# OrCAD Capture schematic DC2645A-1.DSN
size Custom; note: WIDEBAND IQ DEMODULATOR
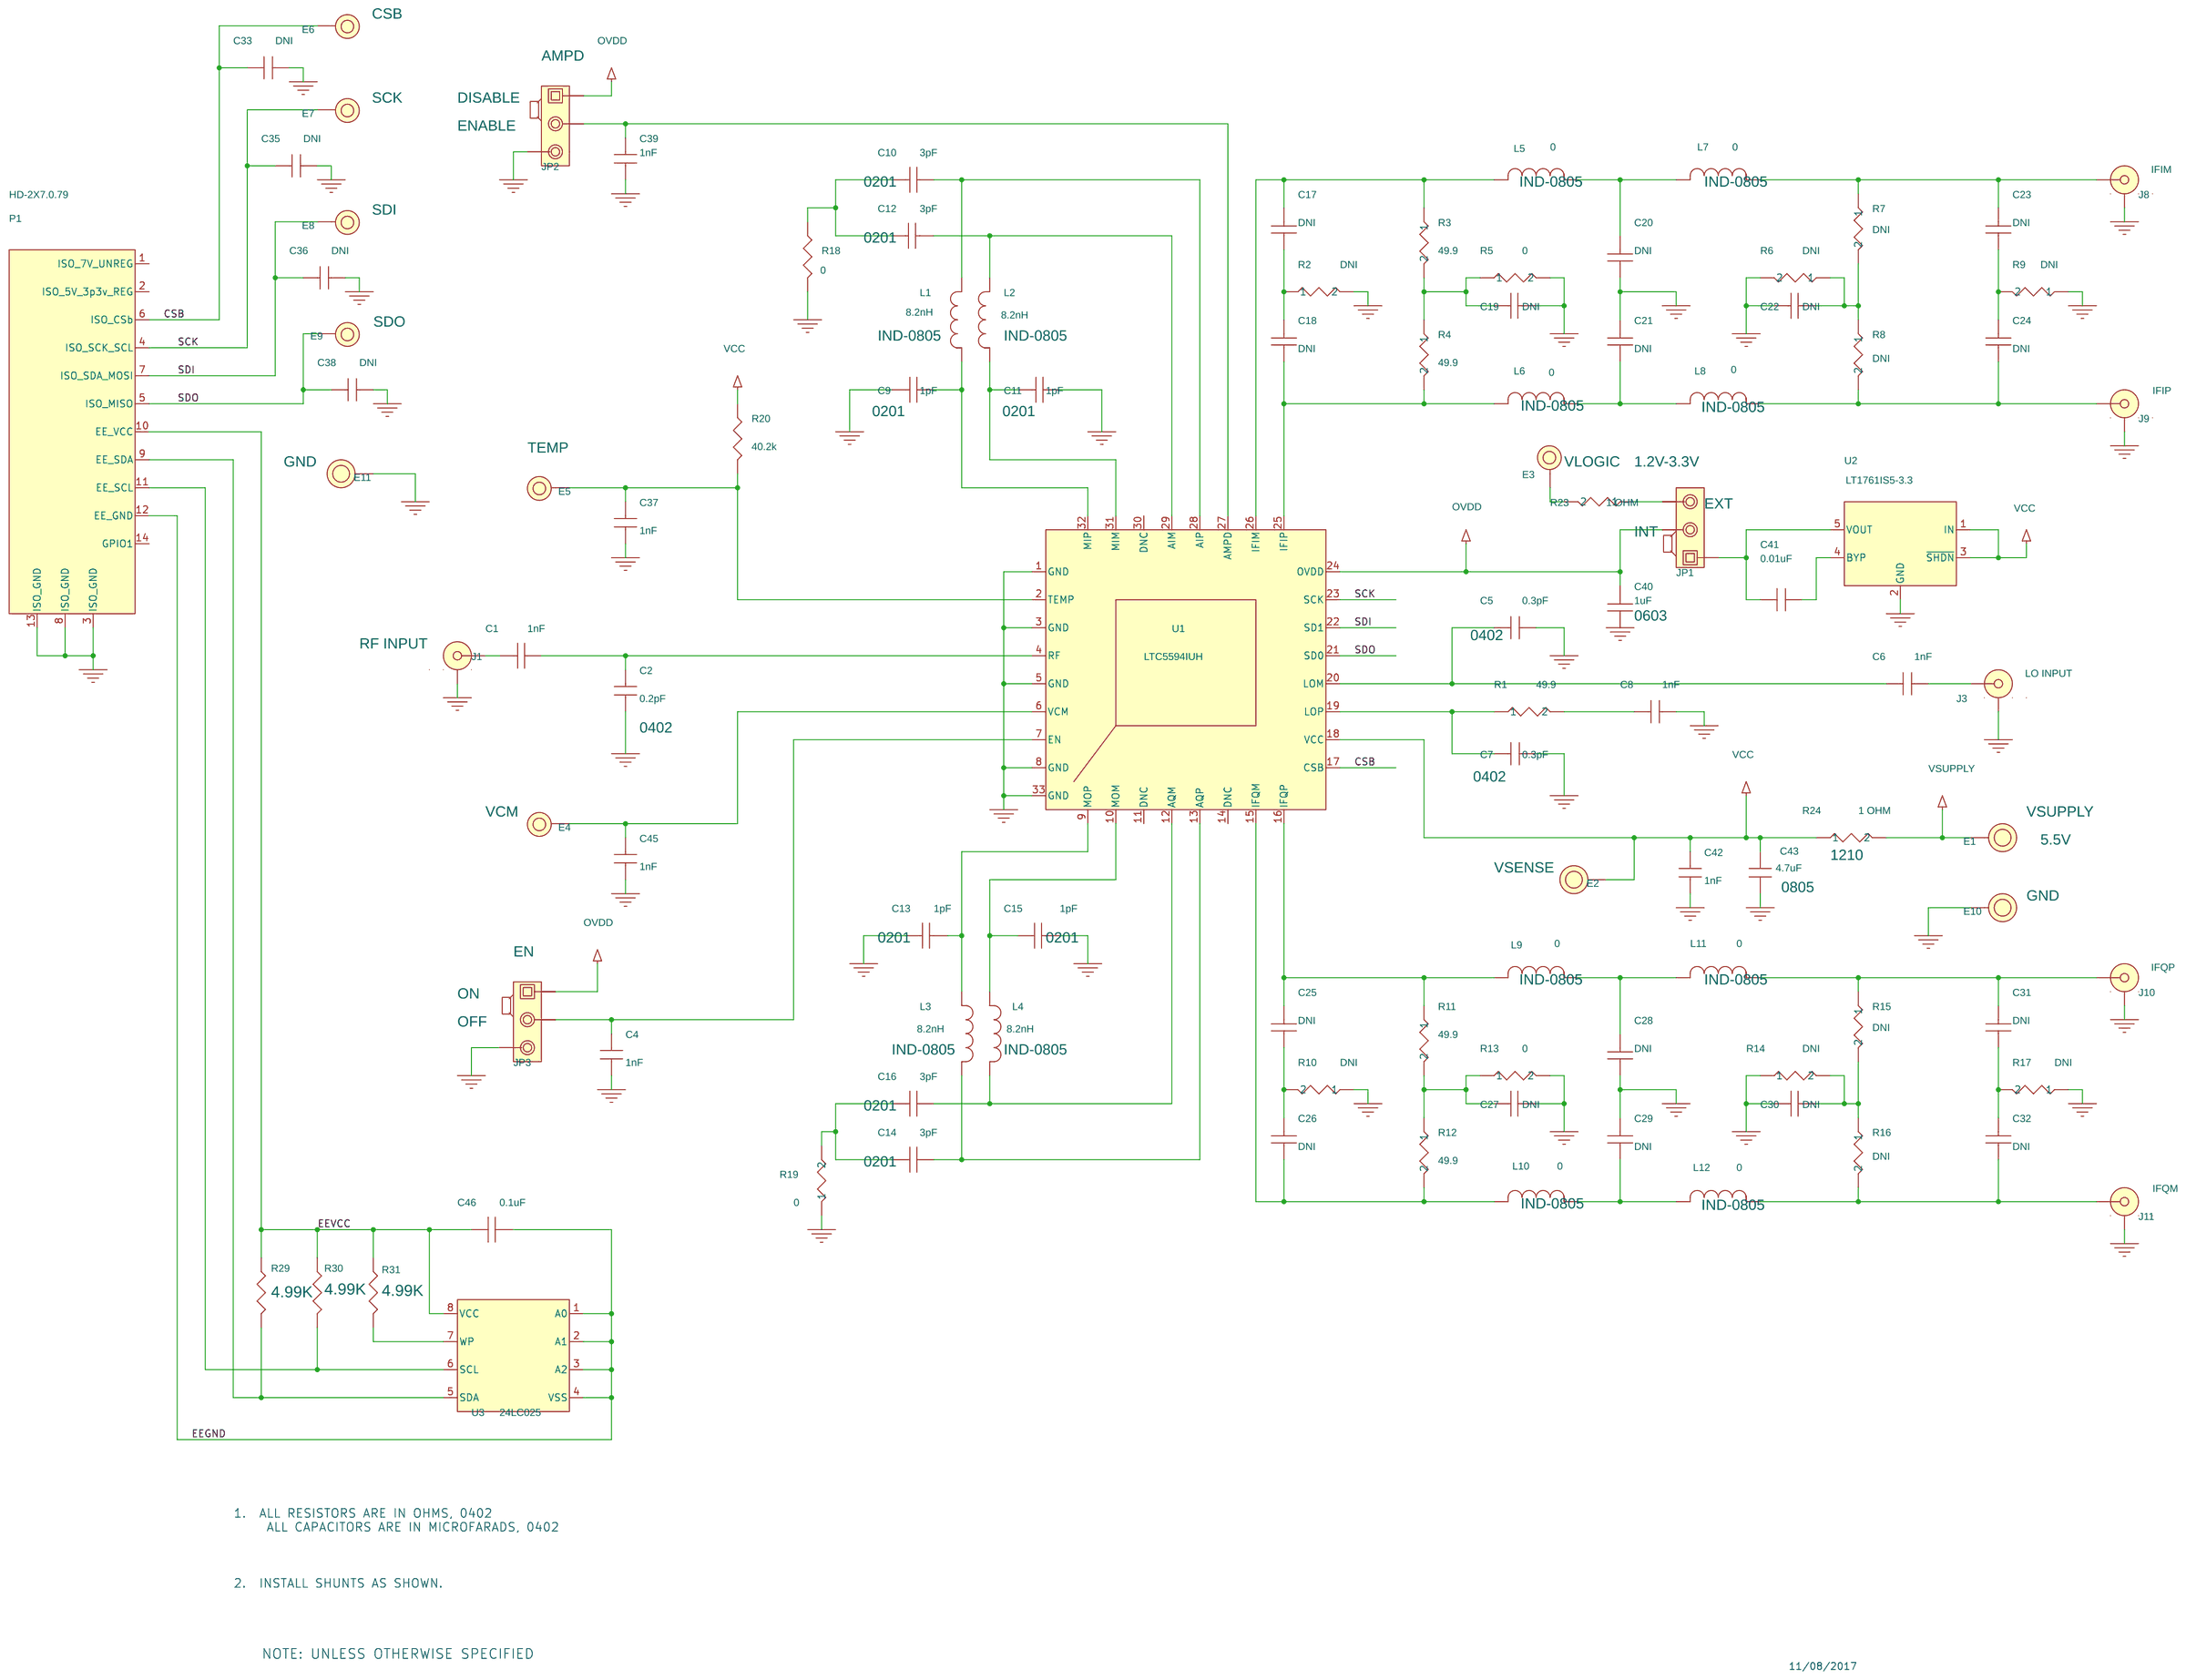
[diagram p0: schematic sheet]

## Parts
C1  1nF  [0402]
C2  0.2pF  [0402]
C4  1nF  [0402]
C5  0.3pF  [0402]
C6  1nF  [0402]
C7  0.3pF  [0402]
C8  1nF  [0402]
C9  1pF  [0201]
C10  3pF  [0201]
C11  1pF  [0201]
C12  3pF  [0201]
C13  1pF  [0201]
C14  3pF  [0201]
C15  1pF  [0201]
C16  3pF  [0201]
C17  DNI  [0402]
C18  DNI  [0402]
C19  DNI  [0402]
C20  DNI  [0402]
C21  DNI  [0402]
C22  DNI  [0402]
C23  DNI  [0402]
C24  DNI  [0402]
C25  DNI  [0402]
C26  DNI  [0402]
C27  DNI  [0402]
C28  DNI  [0402]
C29  DNI  [0402]
C30  DNI  [0402]
C31  DNI  [0402]
C32  DNI  [0402]
C33  DNI  [0402]
C35  DNI  [0402]
C36  DNI  [0402]
C37  1nF  [0402]
C38  DNI  [0402]
C39  1nF  [0402]
C40  1uF  [0603]
C41  0.01uF  [0402]
C42  1nF  [0402]
C43  4.7uF  [0805]
C45  1nF  [0402]
C46  0.1uF  [0402]
E1  MILL MAX 2501  [MILLMAX2501]
E2  MILL MAX 2501  [MILLMAX2501]
E3  MILL MAX 2501  [MILLMAX2308]
E4  MILL MAX 2501  [MILLMAX2308]
E5  MILL MAX 2501  [MILLMAX2308]
E6  MILL MAX 2501  [MILLMAX2308]
E7  MILL MAX 2501  [MILLMAX2308]
E8  MILL MAX 2501  [MILLMAX2308]
E9  MILL MAX 2501  [MILLMAX2308]
E10  MILL MAX 2501  [MILLMAX2501]
E11  MILL MAX 2501  [MILLMAX2501]
J1  CON\SMA-END-E.F.JOHNSON  [CON\SMA-END]
J3  LO INPUT  [CON\SMA-END]
J8  IFIM  [CON\SMA-END]
J9  IFIP  [CON\SMA-END]
J10  IFQP  [CON\SMA-END]
J11  IFQM  [CON\SMA-END]
JP1  3 Pins 2mm Ctrs.  [Samtec\TMM-103-02-L-S]
JP2  3 Pins 2mm Ctrs.  [Samtec\TMM-103-02-L-S]
JP3  3 Pins 2mm Ctrs.  [Samtec\TMM-103-02-L-S]
L1  8.2nH  [IND-0805]
L2  8.2nH  [IND-0805]
L3  8.2nH  [IND-0805]
L4  8.2nH  [IND-0805]
L5  0  [IND-0805]
L6  0  [IND-0805]
L7  0  [IND-0805]
L8  0  [IND-0805]
L9  0  [IND-0805]
L10  0  [IND-0805]
L11  0  [IND-0805]
L12  0  [IND-0805]
P1  HD-2X7.0.79  [HD2X7-079-MOLEX]
R1  49.9  [0402]
R2  DNI  [0402]
R3  49.9  [0402]
R4  49.9  [0402]
R5  0  [0402]
R6  DNI  [0402]
R7  DNI  [0402]
R8  DNI  [0402]
R9  DNI  [0402]
R10  DNI  [0402]
R11  49.9  [0402]
R12  49.9  [0402]
R13  0  [0402]
R14  DNI  [0402]
R15  DNI  [0402]
R16  DNI  [0402]
R17  DNI  [0402]
R18  0  [0201]
R19  0  [0201]
R20  40.2k  [0402]
R23  1 OHM  [0402]
R24  1 OHM  [1210]
R29  4.99K  [0402]
R30  4.99K  [0402]
R31  4.99K  [0402]
U1  LTC5594IUH
U2  LT1761IS5-3.3  [TSOT23-5]
U3  24LC025  [ST-4.4MMTSSOP]
XJP1  2mm Ctrs.
XJP2  2mm Ctrs.
XJP3  2mm Ctrs.

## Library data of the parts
C1 C9-C32 C40 C46 = CAP_NP_0: CAP, 0402 0.1uF 10% 10V X5R; Part Number: AVX 0402ZD104KAT
C2 C4-C8 C33 C35-C39 C41-C43 C45 = CAP0402
E1 = TURRET,__0.093_MTG_HOLE: 1ST: VSUPPLY; LTC#: 260-0003; VOLTAGE: 5.5V
E2 = TURRET,__0.093_MTG_HOLE: 1ST: VSENSE; LTC#: 260-0003; VOLTAGE: 5.5V
E3 = TURRET,_.093_MTG_HOLE: 1: 1.2V-3.3V; VOLTAGE: VLOGIC
E4 = TURRET,_.093_MTG_HOLE: VOLTAGE: VCM
E5 = TURRET,_.093_MTG_HOLE: VOLTAGE: TEMP
E6 = TURRET,_.093_MTG_HOLE: VOLTAGE: CSB
E7 = TURRET,_.093_MTG_HOLE: VOLTAGE: SCK
E8 = TURRET,_.093_MTG_HOLE: VOLTAGE: SDI
E9 = TURRET,_.093_MTG_HOLE: VOLTAGE: SDO
E10 E11 = TURRET,__0.093_MTG_HOLE: 1ST: GND; LTC#: 260-0003; VOLTAGE: 5.5V
J1 = CON_SMA-END-E.F.JOHNSON: 1: RF INPUT
J3 J8-J11 = CON_SMA-END_3: CONN, BNC, SMA 50-OHM EDGE-LANCH; Part Number: E.F.JOHNSON, 142-0701-851
JP1 = HEADER-3X1_1: 1: INT; 2: EXT; 4th Part Field: OVDD
JP2 = HEADER-3X1_0: 1: DISABLE; 2: ENABLE; 4th Part Field: AMPD
JP3 = HEADER-3X1_0: 1: ON; 2: OFF; 4th Part Field: EN
L1-L12 = TOKO-LLQ1608_0
P1 = CONN.,_JTAG,_2X5,_0_0.100
R1 = RES0402_0_19
R2 = RES0402_0_7
R3 = RES0402_0_12
R4 = RES0402_0_3
R5 = RES0402_0_13
R6 = RES0402_0_4
R7 = RES0402_0_14
R8 = RES0402_0_5
R9 = RES0402_0_17
R10 = RES0402_0_6
R11 = RES0402_0
R12 = RES0402_0_18
R13 = RES0402_0_15
R14 = RES0402_0_10
R15 = RES0402_0_11
R16 = RES0402_0_9
R17 = RES0402_0_16
R18 R20 = RESISTOR
R19 = RES0402_0_1
R23 = RES0402_0_8
R24 = RES0402_0_2
R29-R31 = R_1: 0603: 0603; 1%: 1%
U1 = LTC5594IUH_0
U2 = LT1761ES5-SD_1
U3 = 24LC025_0
XJP1-XJP3 = SHUNT,_2MM

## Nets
GND: C2.2 C4.2 C5.2 C7.2 C8.2 C9.1 C11.2 C13.2 C15.1 C19.1 C20.2 C21.1 C22.2 C27.1 C28.2 C29.1 C30.2 C33.2 C35.2 C36.2 C37.2 C38.2 C39.1 C40.2 C42.2 C43.2 C45.2 E10.1 E11.1 J1.2(GND) J1.3(GND) J1.4(GND) J1.5(GND) J3.2(GND) J3.3(GND) J3.4(GND) J3.5(GND) J8.2(GND) J8.3(GND) J8.4(GND) J8.5(GND) J9.2(GND) J9.3(GND) J9.4(GND) J9.5(GND) J10.2(GND) J10.3(GND) J10.4(GND) J10.5(GND) J11.2(GND) J11.3(GND) J11.4(GND) J11.5(GND) JP2.3 JP3.3 P1.3(ISO_GND) P1.8(ISO_GND) P1.13(ISO_GND) R2.2 R5.2 R6.2 R9.1 R10.1 R13.2 R14.1 R17.1 R18.2 R19.1 U1.1(GND) U1.3(GND) U1.5(GND) U1.8(GND) U1.33(GND) U2.2(GND)
VCC: C42.1 C43.1 E2.1 R20.1 R24.1 U1.18(VCC) U2.1(IN) U2.3(~{SHDN})
CSB: C33.1 E6.1 P1.6(ISO_CSb) U1.17(CSB)
EEGND: C46.1 P1.12(EE_GND) U3.1(A0) U3.2(A1) U3.3(A2) U3.4(VSS)
EEVCC: C46.2 P1.10(EE_VCC) R29.2 R30.2 R31.2 U3.8(VCC)
OVDD: C40.1 JP1.2 JP2.1 JP3.1 U1.24(OVDD)
SCK: C35.1 E7.1 P1.4(ISO_SCK_SCL) U1.23(SCK)
SDI: C36.1 E8.1 P1.7(ISO_SDA_MOSI) U1.22(SD1)
SDO: C38.1 E9.1 P1.5(ISO_MISO) U1.21(SD0)
VSUPPLY: E1.1 R24.2
N16666902: C6.1 J3.1(CENTER)
N16733508: C1.2 C2.1 U1.4(RF)
N16733516: C1.1 J1.1(CENTER)
N16739013: C18.2 L6.2 R4.2 U1.25(IFIP)
N16742537: C5.1 C6.2 U1.20(LOM)
N16742555: C7.1 R1.1 U1.19(LOP)
N16744372: C45.1 E4.1 U1.6(VCM)
N16747182: C27.2 R11.2 R12.1 R13.1
N16747254: C26.2 L10.2 R12.2 U1.15(IFQM)
N16747270: C25.2 C26.1 R10.2
N16747474: C30.1 R14.2 R15.2 R16.1
N16747586: C28.1 L9.1 L11.2
N16747590: C31.1 J10.1(CENTER) L11.1 R15.1
N16747598: C32.2 J11.1(CENTER) L12.1 R16.2
N16747606: C29.2 L10.1 L12.2
N16747878: C25.1 L9.2 R11.1 U1.16(IFQP)
N16762120: C9.2 L1.1 U1.32(MIP)
N16764699: C16.2 L4.2 U1.12(AQM)
N16764710: C14.2 L3.2 U1.13(AQP)
N16770840: R31.1 U3.7(WP)
N16770856: P1.11(EE_SCL) R30.1 U3.6(SCL)
N16770884: P1.9(EE_SDA) R29.1 U3.5(SDA)
N16794469: C4.1 JP3.2 U1.7(EN)
N16816230: C41.2 U2.4(BYP)
N16831626: C15.2 L4.1 U1.10(MOM)
N16831628: C13.1 L3.1 U1.9(MOP)
N16842506: C11.1 L2.1 U1.31(MIM)
N16844061: C12.1 L2.2 U1.29(AIM)
N16844065: C10.2 L1.2 U1.28(AIP)
N16845133: C10.1 C12.2 R18.1
N16853322: C37.1 E5.1 R20.2 U1.2(TEMP)
N16875841: C41.1 JP1.1 U2.5(VOUT)
N16876652: E3.1 R23.2
N16876684: JP1.3 R23.1
N16894201: C8.1 R1.2
N16899056: C31.2 C32.1 R17.2
N16902329: C17.1 L5.2 R3.1 U1.26(IFIM)
N16902333: C19.2 R3.2 R4.1 R5.1
N16902351: C17.2 C18.1 R2.1
N16902357: C22.1 R6.1 R7.2 R8.1
N16902371: C23.2 C24.1 R9.2
N16902397: C23.1 J8.1(CENTER) L7.1 R7.1
N16902401: C24.2 J9.1(CENTER) L8.1 R8.2
N16902581: C20.1 L5.1 L7.2
N16902591: C21.2 L6.1 L8.2
N16931460: C14.1 C16.1 R19.2
N16940220: C39.2 JP2.2 U1.27(AMPD)

Not connected (* = marked no-connect by the designer): P1 1(ISO_7V_UNREG) 2(ISO_5V_3p3v_REG) 14(GPIO1); U1 11(DNC) 14(DNC) 30(DNC)

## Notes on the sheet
- 1.  ALL RESISTORS ARE IN OHMS, 0402
       ALL CAPACITORS ARE IN MICROFARADS, 0402
- 2.  INSTALL SHUNTS AS SHOWN.
- NOTE: UNLESS OTHERWISE SPECIFIED
- 11/08/2017
